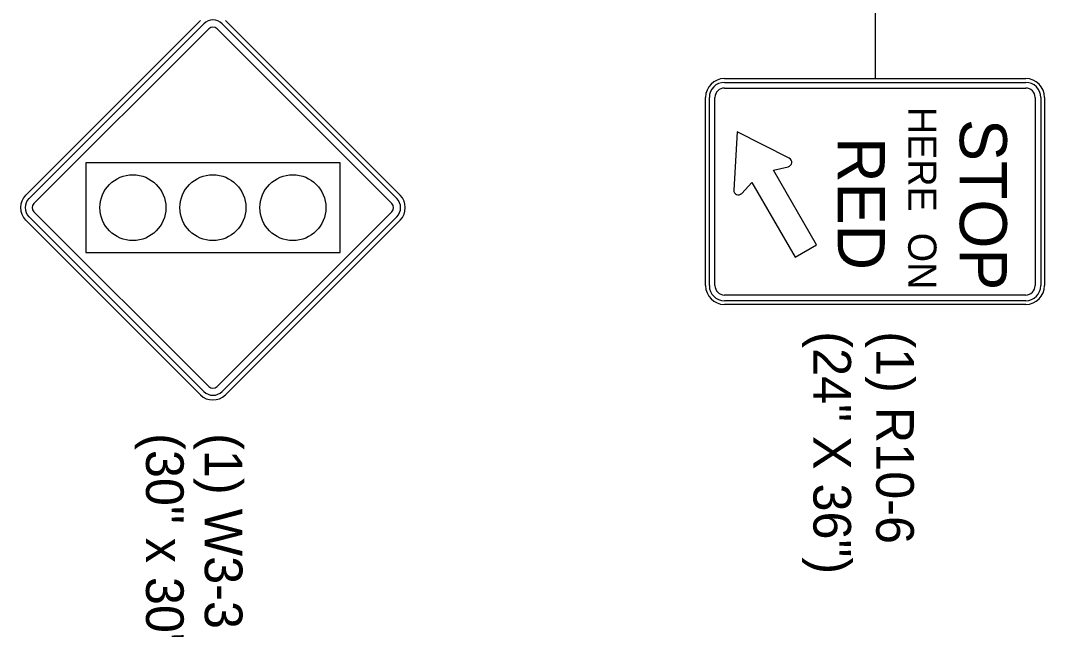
# Model space of a CAD drawing. Extents: x 1927831 to 1930787, y 596452 to 597699.
# Drawn here: x 1928474.6 to 1928637.7, y 597360.2 to 597457.3 of the extents above; entities that cross this region are included whole.
import ezdxf

# ---------------------------------------------------------------- set-up
doc = ezdxf.new("R2010")
doc.units = 0
doc.layers.add('P_TC_Signs_Permanent', color=7, linetype='Continuous')
doc.layers.add('R_Annotation', color=7, linetype='Continuous')

msp = doc.modelspace()

# ---------------------------------------------------------------- linework, layer by layer
at = {"layer": 'P_TC_Signs_Permanent'}
for p, q in [((1928475.4, 597429.47), (1928503.24, 597457.31)), ((1928475.93, 597428.94), (1928503.77, 597456.78)), ((1928506.69, 597456.78), (1928534.53, 597428.94)), ((1928507.22, 597457.31), (1928535.06, 597429.47)), ((1928504.56, 597455.99), (1928476.72, 597428.15)), ((1928533.73, 597428.15), (1928505.89, 597455.99)), ((1928586.72, 597448.05), (1928634.72, 597448.05)), ((1928586.72, 597447.45), (1928634.72, 597447.45)), ((1928586.72, 597446.55), (1928634.72, 597446.55)), ((1928583.72, 597415.05), (1928583.72, 597445.05)), ((1928584.32, 597415.05), (1928584.32, 597445.05)), ((1928585.22, 597415.05), (1928585.22, 597445.05)), ((1928636.22, 597445.05), (1928636.22, 597415.05)), ((1928637.12, 597445.05), (1928637.12, 597415.05)), ((1928637.72, 597445.05), (1928637.72, 597415.05)), ((1928503.77, 597398.18), (1928475.93, 597426.02)), ((1928476.72, 597426.82), (1928504.56, 597398.98)), ((1928505.89, 597398.98), (1928533.73, 597426.82)), ((1928534.53, 597426.02), (1928506.69, 597398.18)), ((1928503.24, 597397.65), (1928475.4, 597425.49)), ((1928535.06, 597425.49), (1928507.22, 597397.65)), ((1928634.72, 597413.55), (1928586.72, 597413.55)), ((1928634.72, 597412.65), (1928586.72, 597412.65)), ((1928634.72, 597412.05), (1928586.72, 597412.05))]:
    msp.add_line(p, q, dxfattribs=at)
for points in [[(1928597.06, 597435.35), (1928588.73, 597439.55), (1928588.22, 597430.28)], [(1928589.47, 597429.75), (1928591.11, 597431.49), (1928598, 597419.57), (1928601.41, 597421.54), (1928594.52, 597433.46), (1928596.89, 597434.01)]]:
    msp.add_lwpolyline(points, dxfattribs=at)
msp.add_lwpolyline([(1928484.98, 597434.61), (1928484.98, 597420.36), (1928525.48, 597420.36), (1928525.48, 597434.61)], close=True, dxfattribs=at)
for centre in [(1928492.48, 597427.48), (1928505.23, 597427.48), (1928517.98, 597427.48)]:
    msp.add_circle(centre, 5.25, dxfattribs=at)
for centre, radius, start, end in [((1928505.23, 597455.33), 2.06, 45, 135), ((1928505.23, 597455.33), 0.938, 45, 135), ((1928586.72, 597445.05), 3, 90, 180), ((1928586.72, 597445.05), 2.4, 90, 180), ((1928634.72, 597445.05), 3, 360, 90), ((1928634.72, 597445.05), 2.4, 360, 90), ((1928586.72, 597445.05), 1.5, 90, 180), ((1928634.72, 597445.05), 1.5, 360, 90), ((1928596.73, 597434.71), 0.72, 283.0349, 63.2286), ((1928477.38, 597427.48), 2.81, 135, 225), ((1928477.38, 597427.48), 2.06, 135, 225), ((1928533.07, 597427.48), 2.06, 315, 45), ((1928533.07, 597427.48), 2.81, 315, 45), ((1928588.94, 597430.24), 0.72, 176.857, 316.6377), ((1928477.38, 597427.48), 0.938, 135, 225), ((1928533.07, 597427.48), 0.938, 315, 45), ((1928586.72, 597415.05), 3, 180, 270), ((1928586.72, 597415.05), 2.4, 180, 270), ((1928586.72, 597415.05), 1.5, 180, 270), ((1928634.72, 597415.05), 3, 270, 360), ((1928634.72, 597415.05), 2.4, 270, 360), ((1928634.72, 597415.05), 1.5, 270, 360), ((1928505.23, 597399.64), 2.06, 225, 315), ((1928505.23, 597399.64), 0.938, 225, 315), ((1928505.23, 597399.64), 2.81, 225, 315)]:
    msp.add_arc(centre, radius, start, end, dxfattribs=at)
at = {"layer": 'R_Annotation'}
msp.add_line((1928610.72, 597465.08), (1928610.72, 597448.05), dxfattribs=at)

# ---------------------------------------------------------------- texts
at = {"layer": 'P_TC_Signs_Permanent'}
for s, height, p in [('HERE  ON', 4.5, (1928616, 597443.55)), ('STOP', 7.5, (1928624.22, 597441.61)), ('RED', 7.5, (1928604.78, 597438.72))]:
    msp.add_text(s, height=height, rotation=270, dxfattribs=at).set_placement(p)
at = {"layer": 'R_Annotation'}
for s, height, p in [('(24" X 36")', 5.9996, (1928600.89, 597407.77)), ('(1) R10-6', 6, (1928610.9, 597407.77)), ('(30" x 30")', 5.9996, (1928494.57, 597391.54)), ('(1) W3-3', 6, (1928503.93, 597391.54))]:
    msp.add_text(s, height=height, rotation=270, dxfattribs=at).set_placement(p)

doc.saveas('drawing.dxf')
